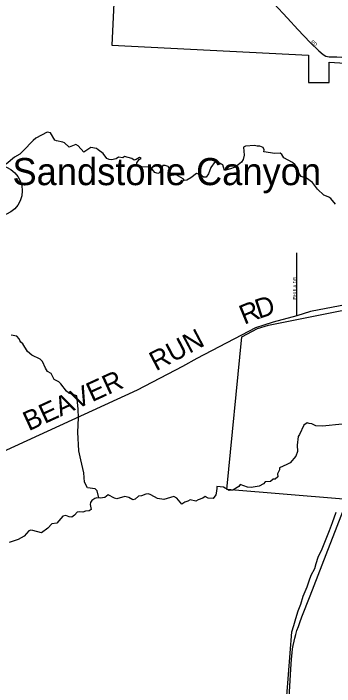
# Model space of a CAD drawing. Extents: x 0 to 40.4, y 0 to 22.
# Drawn here: x 5.767 to 6.701, y 17.952 to 19.912 of the extents above; entities that cross this region are included whole.
import ezdxf

# ---------------------------------------------------------------- set-up
doc = ezdxf.new("R2010")
doc.units = 0
for name, color, linetype in [('GM_X_City_Street', 7, 'Continuous'), ('GM_X_City_Street_Text', 7, 'Continuous'), ('GM_X_Corporation', 7, 'Continuous'), ('GM_X_Minor_River', 7, 'Continuous'), ('GM_X_Rail_Line', 7, 'Continuous'), ('GM_X_Township_Road', 7, 'Continuous'), ('GM_X_Township_Road_Text', 7, 'Continuous'), ('GM_X_Township_Subdivision', 7, 'Continuous'), ('GM_X_Township_Subdivision_Text', 7, 'Continuous'), ('GM_X_Unincorporated', 7, 'Continuous'), ('GM_X_Unincorporated_Text', 7, 'Continuous')]:
    doc.layers.add(name, color=color, linetype=linetype)

msp = doc.modelspace()

# ---------------------------------------------------------------- linework, layer by layer
at = {"layer": 'GM_X_City_Street'}
msp.add_lwpolyline([(6.2498, 20.2011), (6.296, 20.166), (6.3199, 20.1487), (6.364, 20.1154), (6.4116, 20.0767), (6.4466, 20.0492), (6.4587, 20.036), (6.4681, 20.0231), (6.4842, 19.9981), (6.5013, 19.9731), (6.5145, 19.9536), (6.5241, 19.9412), (6.5642, 19.8984), (6.594, 19.8649), (6.6301, 19.8274), (6.6555, 19.8037), (6.6684, 19.7925), (6.6763, 19.7881), (6.6859, 19.7856), (6.7077, 19.7856), (6.7817, 19.781), (7.0654, 19.7611)], dxfattribs=at)
at = {"layer": 'GM_X_Corporation'}
for points in [[(6.0642, 20.0658), (6.0532, 19.8193), (6.6256, 19.7906), (6.6256, 19.7108), (6.6852, 19.7108), (6.6852, 19.7705), (7.0552, 19.7467)], [(6.7268, 18.4978), (6.3873, 18.5253), (6.4313, 18.9704), (6.4766, 18.9944), (6.5092, 19.0041), (6.932, 19.0891)], [(6.5433, 17.6757), (6.5768, 18.1113), (6.5828, 18.1297), (6.5885, 18.1502), (6.5955, 18.1723), (6.6034, 18.1916), (6.6102, 18.2144), (6.6216, 18.2417), (6.6272, 18.2597), (6.6332, 18.2765), (6.6434, 18.2956), (6.6477, 18.3096), (6.6535, 18.3284), (6.6651, 18.3527), (6.6752, 18.3774), (6.6866, 18.4058), (6.6956, 18.4294), (6.7057, 18.4599)]]:
    msp.add_lwpolyline(points, dxfattribs=at)
at = {"layer": 'GM_X_Minor_River'}
for points in [[(6.1178, 19.4845), (6.1115, 19.4895), (6.0898, 19.4953), (6.0845, 19.4919), (6.0728, 19.4931), (6.0652, 19.4889), (6.0523, 19.486), (6.0447, 19.4867), (6.0382, 19.4894), (6.0273, 19.5039), (6.0129, 19.5153), (6.008, 19.5187), (5.9917, 19.5214), (5.9715, 19.5082), (5.9545, 19.5265), (5.9485, 19.5303), (5.9287, 19.5228), (5.9151, 19.5354), (5.9102, 19.5369), (5.8916, 19.5408), (5.8867, 19.5427), (5.8742, 19.5647), (5.8651, 19.5667), (5.8321, 19.549), (5.8237, 19.5425), (5.7948, 19.5119), (5.7849, 19.5021), (5.77, 19.4934), (5.7453, 19.4734)], [(6.7036, 19.3571), (6.69, 19.3731), (6.6847, 19.3769), (6.6776, 19.3799), (6.67, 19.3833), (6.6515, 19.4004), (6.6368, 19.4194), (6.6198, 19.432), (6.604, 19.4373), (6.5949, 19.451), (6.5927, 19.4574), (6.5866, 19.4711), (6.5791, 19.4783), (6.5538, 19.4912), (6.5477, 19.5011), (6.5428, 19.5049), (6.5273, 19.5046), (6.4956, 19.5095), (6.4964, 19.5145), (6.4937, 19.5213), (6.4835, 19.5251), (6.476, 19.5259), (6.468, 19.5278), (6.4419, 19.5259), (6.4359, 19.5225), (6.4377, 19.4994), (6.435, 19.4865), (6.4305, 19.4793), (6.4161, 19.4676), (6.4089, 19.4638), (6.3983, 19.4593), (6.3805, 19.4544), (6.3764, 19.4711), (6.3677, 19.4757), (6.3621, 19.4761), (6.3537, 19.4806), (6.3412, 19.4632), (6.334, 19.4446), (6.3272, 19.4356), (6.32, 19.4348), (6.3109, 19.442), (6.3057, 19.4436), (6.2992, 19.4458), (6.2833, 19.433), (6.2708, 19.4262), (6.2648, 19.4251), (6.2606, 19.4307), (6.2402, 19.4422), (6.2198, 19.4395), (6.2191, 19.449), (6.2206, 19.4593), (6.2165, 19.4661), (6.2085, 19.4691), (6.2013, 19.4695), (6.1915, 19.4479), (6.1866, 19.4457), (6.1779, 19.4491), (6.1669, 19.4632), (6.1609, 19.4647), (6.1401, 19.4651), (6.1318, 19.467), (6.1257, 19.4682), (6.1254, 19.4773), (6.1326, 19.4867), (6.1379, 19.4901), (6.133, 19.4924), (6.1239, 19.4864), (6.1178, 19.4845)], [(6.0149, 18.5009), (6.0106, 18.5216), (6.0046, 18.5277), (5.9818, 18.5305), (5.9732, 18.5472), (5.971, 18.5741), (5.9631, 18.6117), (5.9568, 18.6386), (5.9539, 18.6921), (5.9556, 18.7342), (5.9549, 18.76), (5.9527, 18.7797), (5.9509, 18.7983), (5.9278, 18.806), (5.921, 18.8121), (5.9047, 18.833), (5.8983, 18.8391), (5.885, 18.846), (5.8768, 18.8631), (5.8654, 18.8696), (5.8597, 18.8787), (5.8511, 18.8988), (5.8447, 18.9049), (5.82, 18.9168), (5.8072, 18.9271), (5.794, 18.9499), (5.7883, 18.9548), (5.7853, 18.9597), (5.783, 18.9647), (5.7766, 18.9723), (5.7595, 18.9754)], [(6.7235, 18.7163), (6.666, 18.71), (6.6467, 18.7112), (6.6347, 18.7165), (6.6271, 18.718), (6.6211, 18.7199), (6.612, 18.7131), (6.5994, 18.6855), (6.5956, 18.6802), (6.5922, 18.6544), (6.5929, 18.6362), (6.5887, 18.6226), (6.5717, 18.6033), (6.5626, 18.5983), (6.5414, 18.5889), (6.541, 18.5832), (6.5353, 18.5711), (6.5357, 18.5624), (6.5285, 18.5556), (6.5228, 18.5552), (6.5152, 18.5491), (6.4997, 18.548), (6.4948, 18.5416), (6.4815, 18.5352), (6.4706, 18.5337), (6.4589, 18.5318), (6.4483, 18.5322), (6.426, 18.5398), (6.4222, 18.5342), (6.4051, 18.5236), (6.3946, 18.5228), (6.3779, 18.532), (6.3587, 18.5347), (6.3583, 18.5297), (6.3575, 18.521), (6.3556, 18.5104), (6.3476, 18.499), (6.3329, 18.5002), (6.3246, 18.5048), (6.3178, 18.5002), (6.3041, 18.4953), (6.2973, 18.4912), (6.2807, 18.4954), (6.2743, 18.4916), (6.2652, 18.489), (6.2569, 18.4829), (6.2421, 18.5004), (6.2338, 18.5053), (6.2047, 18.4967), (6.1858, 18.499), (6.1665, 18.5104), (6.1601, 18.5127), (6.1518, 18.5123), (6.1397, 18.5074), (6.131, 18.5063), (6.1211, 18.4972), (6.1136, 18.4953)], [(6.1136, 18.4953), (6.1024, 18.5023), (6.0906, 18.5047), (6.0678, 18.4983), (6.061, 18.5002), (6.0425, 18.5105), (6.0322, 18.5018), (6.0185, 18.5008), (6.0094, 18.5012), (6.0033, 18.4997), (5.995, 18.494), (5.9904, 18.4876), (5.99, 18.4823), (5.9926, 18.4675), (5.9873, 18.4633), (5.9767, 18.4626), (5.9687, 18.4592), (5.9585, 18.4608), (5.9524, 18.46), (5.9444, 18.451), (5.9364, 18.4449), (5.9284, 18.4461), (5.919, 18.4499), (5.9106, 18.4477), (5.8927, 18.4276), (5.8779, 18.4254), (5.8669, 18.4129), (5.8486, 18.399), (5.8225, 18.4063), (5.8168, 18.407), (5.8115, 18.4052), (5.7974, 18.3901), (5.7803, 18.3795), (5.7537, 18.3712)]]:
    msp.add_lwpolyline(points, dxfattribs=at)
at = {"layer": 'GM_X_Rail_Line'}
msp.add_lwpolyline([(6.5658, 17.8694), (6.5737, 18.0027), (6.5759, 18.0318), (6.5776, 18.0502), (6.5791, 18.061), (6.581, 18.0716), (6.5835, 18.0842), (6.5858, 18.093), (6.5884, 18.1032), (6.5918, 18.1147), (6.596, 18.127), (6.6004, 18.1386), (6.6063, 18.1544), (6.6304, 18.2163), (6.677, 18.3363), (6.7413, 18.5013)], dxfattribs=at)
at = {"layer": 'GM_X_Township_Road'}
msp.add_lwpolyline([(7.0098, 19.1185), (6.9971, 19.1141), (6.9476, 19.1035), (6.8196, 19.0802), (6.6311, 19.0439), (6.5915, 19.0309), (6.523, 19.0125), (6.4954, 19.0041), (6.4712, 18.9966), (6.4303, 18.9749), (6.3004, 18.9068), (6.2582, 18.8838), (6.1264, 18.8144), (5.7095, 18.6233)], dxfattribs=at)
at = {"layer": 'GM_X_Township_Subdivision'}
msp.add_lwpolyline([(6.5915, 19.0309), (6.5918, 19.2147)], dxfattribs=at)
at = {"layer": 'GM_X_Unincorporated'}
msp.add_circle((5.7176, 19.3957), 0.0744, dxfattribs=at)

# ---------------------------------------------------------------- texts
at = {"layer": 'GM_X_City_Street_Text'}
msp.add_text('RD', height=0.00947, rotation=319.3961, dxfattribs=at).set_placement((6.6315, 19.8284))
at = {"layer": 'GM_X_Township_Road_Text'}
for s, height, rotation, p in [('D', 0.0568, 17.7345, (6.4805, 19.0223)), ('R', 0.0568, 22.3443, (6.4385, 19.005)), ('RUN', 0.05682, 27.7842, (6.1814, 18.8693)), ('BEAVER', 0.05682, 24.643, (5.811, 18.6949))]:
    msp.add_text(s, height=height, rotation=rotation, dxfattribs=at).set_placement(p)
at = {"layer": 'GM_X_Township_Subdivision_Text'}
msp.add_text('EHULA DR', height=0.00947, rotation=90, dxfattribs=at).set_placement((6.5902, 19.0787))
at = {"layer": 'GM_X_Unincorporated_Text'}
msp.add_text('Sandstone Canyon', height=0.078977, rotation=0, dxfattribs=at).set_placement((5.7636, 19.412))

doc.saveas('drawing.dxf')
